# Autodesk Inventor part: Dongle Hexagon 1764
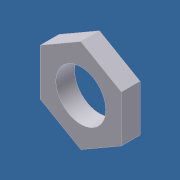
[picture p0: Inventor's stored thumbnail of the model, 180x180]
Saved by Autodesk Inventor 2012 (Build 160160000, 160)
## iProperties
Created: 2010-01
Part Number: Dongle Hexagon 1764
Document SubType Name: Modeling
Designer: jgehrig
Density: 1 g/cm^3
Material: Default
Author: jgehrig
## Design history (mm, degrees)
sketch "Sketch1"
  geometry: L1 (0, 4.766)-(4.127, 2.383); L2 (4.127, 2.383)-(4.128, -2.383); L3 (4.128, -2.383)-(0, -4.766); L4 (0, -4.766)-(-4.128, -2.383); L5 (-4.128, -2.383)-(-4.128, 2.383); L6 (-4.128, 2.383)-(0, 4.766); C1 r 2.54 at (0, 0); 2 further points
  constraints: 12 end point, 2 coincident, 1 centre point, 13 other
  dimensions: "d0" = 8.255 distance between parallel lines of L2 L5; "d1" = 5.08 diameter of C1
extrude "Extrusion1" new body sketch "Sketch1" distance "d2" = 1.905; taper "d3" = 0 deg
body "Solid1"
